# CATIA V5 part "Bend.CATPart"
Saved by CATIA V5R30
Part number: Bend
Bounding box of the stored display mesh (mm): x -50 to 50, y -150 to 15, z -50 to 115
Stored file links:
  D:\PROJECTS\CATIA V56R 2020\Resources\Parts File\c12_catia_v5_6r2020_prt\c12_catia_v5-6r2020 figr_12-39\Bend.CATPart
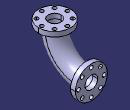
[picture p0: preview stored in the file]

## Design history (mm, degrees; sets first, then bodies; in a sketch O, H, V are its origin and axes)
Body1 (main body)
  Sketch1 on yz-plane, origin (0, 0, 0), H (0, 1, 0), V (0, 0, 1)
    arc A1 centre (0, 100) radius 100 from (-100, 100) to (0, 0) ccw
    point P1 (0, 100)
    coincidence: P1 V
  Sketch2 on zx-plane, origin (0, 0, 0), H (-1, 0, 0), V (0, 0, 1)
    circle A1 centre (0, 0) radius 30
    point P1 (0, -30)
    radius A1 = 30
    coincidence: A1 P1, P1 V
  Rib1: profile Sketch2, centre curve Sketch1
  Sketch3 on face of Rib1, origin (0, 0, 0), H (-1, 0, 0), V (0, 0, 1)
    circle A1 centre (0, 0) radius 50
    point P1 (0, -50)
    radius A1 = 50
    coincidence: A1 P1, P1 V
  Pad1: profile Sketch3, direction (0, 1, 0), length 15
  Sketch4 on face of Rib1, origin (0, 0, 100), H (1, 0, 0), V (0, 1, 0)
    circle A1 centre (0, -100) radius 50
    point P1 (0, -100)
    reference projected circle E1 centre (0, -100) radius 30 from edge [face of Rib1 | face of Rib1]
    radius A1 = 50
    coincidence: P1 V
    concentricity: A1 E1
  Pad2: profile Sketch4, direction (0, 0, 1), length 15
  Sketch5 on face of Pad1, origin (0, 15, 0), H (-1, 0, 0), V (0, 0, 1)
    circle A1 centre (0, 0) radius 20
    radius A1 = 20
  Sketch6 on yz-plane, origin (0, 0, 0), H (0, 1, 0), V (0, 0, 1)
    projected arc E1 centre (0, 100) radius 100 from (-100, 100) to (0, 0) ccw from edge of Sketch1
    line L1 (-100, 100) -> (-100, 115)
    point P3 (-100, 115)
    line L2 (0, 0) -> (15, 0)
    point P4 (15, 0)
    reference projected line E2 (15, 50) -> (15, -50) from edge [face of Pad1 | face of Pad1]
    reference projected line E3 (-50, 115) -> (-150, 115) from edge [face of Pad2 | face of Pad2]
    tangency: L1 E1, L2 E1
    coincidence: P4 E2, P3 E3
  Slot1: profile Sketch5, centre curve Sketch6
  Sketch7 on face of Pad1, origin (0, 15, 0), H (-1, 0, 0), V (0, 0, 1)
    circle A1 centre (0, -40) radius 6
    point P1 (0, -40)
    radius A1 = 6
    distance H P1 = 40
    coincidence: P1 V
  Pocket1: profile Sketch7, direction (0, -1, 0), length 15
  CircPattern1: of Pocket1, instances 8, angular step 45, axis from face of Pad1
  Sketch8 on face of Pad2, origin (0, 0, 115), H (1, 0, 0), V (0, 1, 0)
    circle A1 centre (0, -140) radius 6
    point P1 (0, -140)
    reference projected point E1 (0, -100) from vertex of Sketch1
    radius A1 = 6
    distance E1 P1 = 40
    coincidence: P1 V
  Pocket2: profile Sketch8, direction (0, 0, -1), length 15
  CircPattern2: of Pocket2, instances 8, angular step 45, axis from face of Pad2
